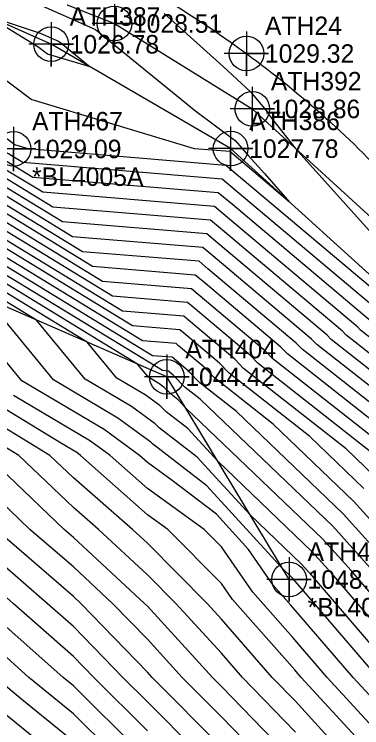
# Model space of a CAD drawing. Extents: x 1213164 to 1213550, y 766120 to 766870.
# Drawn here: x 1213252 to 1213299, y 766303.2 to 766399.6 of the extents above; entities that cross this region are included whole.
import ezdxf

# ---------------------------------------------------------------- set-up
doc = ezdxf.new("R2010")
doc.units = 0
for name, color, linetype in [('Default', 7, 'Continuous'), ('Exist DTM Breakline', 7, 'Continuous'), ('Exist DTM Breakline Cogo Comment', 7, 'Continuous'), ('Exist DTM Breakline Cogo Elevation', 7, 'Continuous'), ('Exist DTM Breakline Cogo Number', 7, 'Continuous'), ('Exist DTM Breakline Cogo Point CELL', 7, 'Continuous'), ('Exist DTM QL2 LIDAR Elevation Point', 7, 'Continuous'), ('Exist DTM Regular Point Cogo Elevation', 7, 'Continuous'), ('Exist DTM Regular Point Cogo Number', 7, 'Continuous'), ('Exist Roads EOP', 7, 'Continuous'), ('Exist Roads EOP Cogo Point CELL', 7, 'Continuous')]:
    doc.layers.add(name, color=color, linetype=linetype)

msp = doc.modelspace()

# ---------------------------------------------------------------- linework, layer by layer
at = {"layer": 'Default'}
for points in [[(1213302.597, 766358.408), (1213282.153, 766375.636), (1213280.103, 766377.363), (1213253.141, 766379.599), (1213251.598, 766380.538), (1213251.233, 766380.76), (1213231.678, 766390.516), (1213231.474, 766390.617), (1213230.808, 766390.964), (1213207.579, 766408.748)], [(1213252.099, 766381.968), (1213238.569, 766392.051), (1213230.917, 766396.699), (1213230.271, 766397.092), (1213210.05, 766409.212)], [(1213300.518, 766357.868), (1213281.492, 766373.902), (1213279.584, 766375.509), (1213254.492, 766377.59), (1213251.259, 766379.558), (1213250.495, 766380.022), (1213231.934, 766389.283), (1213230.499, 766389.988), (1213225.821, 766392.426), (1213206.352, 766407.332)], [(1213304.578, 766352.413), (1213298.807, 766356.947), (1213298.439, 766357.329), (1213280.831, 766372.168), (1213279.065, 766373.656), (1213255.843, 766375.581), (1213250.92, 766378.578), (1213249.758, 766379.285), (1213232.19, 766388.05), (1213229.523, 766389.36), (1213220.835, 766393.889), (1213205.126, 766405.916)], [(1213304.23, 766350.488), (1213296.832, 766356.3), (1213296.361, 766356.79), (1213280.17, 766370.434), (1213278.547, 766371.802), (1213257.194, 766373.572), (1213250.581, 766377.597), (1213249.02, 766378.548), (1213232.445, 766386.817), (1213228.548, 766388.731), (1213215.848, 766395.352), (1213203.899, 766404.5)], [(1213248.618, 766403.962), (1213263.002, 766397.56), (1213276.559, 766386.527), (1213281.848, 766382.566), (1213283.669, 766380.515), (1213285.825, 766378.11), (1213289.231, 766374.252), (1213283.474, 766379.104), (1213281.14, 766381.071), (1213276.351, 766381.468), (1213254.307, 766388.113), (1213246.883, 766393.646), (1213230.055, 766403.868)], [(1213303.882, 766348.563), (1213294.857, 766355.653), (1213294.282, 766356.251), (1213279.509, 766368.7), (1213278.028, 766369.948), (1213258.545, 766371.563), (1213250.242, 766376.617), (1213248.282, 766377.811), (1213232.701, 766385.584), (1213227.572, 766388.103), (1213210.861, 766396.814), (1213202.672, 766403.084)], [(1213303.534, 766346.638), (1213292.883, 766355.006), (1213292.204, 766355.711), (1213278.849, 766366.966), (1213277.51, 766368.094), (1213259.896, 766369.555), (1213249.903, 766375.637), (1213247.544, 766377.073), (1213232.957, 766384.351), (1213226.597, 766387.474), (1213205.874, 766398.277), (1213201.445, 766401.668)], [(1213305.353, 766325.548), (1213297.859, 766333.832), (1213287.001, 766344.237), (1213279.059, 766350.477), (1213277.654, 766351.936), (1213274.223, 766354.827), (1213273.879, 766355.117), (1213269.354, 766355.492), (1213247.531, 766368.776), (1213242.379, 766371.912), (1213234.746, 766375.72), (1213219.769, 766383.075), (1213206.226, 766390.135), (1213197.148, 766393.231), (1213195.169, 766395.169), (1213190, 766397.563), (1213181.204, 766400)], [(1213299.261, 766335.539), (1213291.938, 766342.557), (1213281.033, 766351.124), (1213279.733, 766352.475), (1213274.884, 766356.561), (1213274.398, 766356.971), (1213268.003, 766357.501), (1213247.87, 766369.756), (1213243.117, 766372.649), (1213234.49, 766376.953), (1213220.745, 766383.704), (1213205.157, 766391.829), (1213197.638, 766394.394), (1213195.999, 766395.999), (1213190, 766398.778), (1213185.588, 766400)], [(1213300.664, 766337.246), (1213296.875, 766340.877), (1213283.008, 766351.771), (1213281.811, 766353.015), (1213275.545, 766358.295), (1213274.916, 766358.825), (1213266.652, 766359.51), (1213248.209, 766370.736), (1213243.855, 766373.387), (1213234.235, 766378.186), (1213221.72, 766384.332), (1213204.087, 766393.524), (1213198.128, 766395.556), (1213196.828, 766396.828), (1213190, 766399.992)], [(1213301.812, 766339.197), (1213284.983, 766352.418), (1213283.89, 766353.554), (1213276.205, 766360.029), (1213275.435, 766360.679), (1213265.301, 766361.519), (1213248.548, 766371.716), (1213244.593, 766374.124), (1213233.979, 766379.419), (1213222.695, 766384.961), (1213203.018, 766395.218), (1213198.618, 766396.719), (1213197.658, 766397.658), (1213192.603, 766400)], [(1213302.49, 766340.863), (1213286.958, 766353.065), (1213285.968, 766354.093), (1213276.866, 766361.763), (1213275.954, 766362.533), (1213263.95, 766363.528), (1213248.887, 766372.697), (1213245.33, 766374.861), (1213233.723, 766380.652), (1213223.671, 766385.589), (1213201.949, 766396.913), (1213199.107, 766397.882), (1213198.488, 766398.488), (1213195.224, 766400)], [(1213302.838, 766342.788), (1213288.933, 766353.712), (1213288.047, 766354.633), (1213277.527, 766363.498), (1213276.472, 766364.386), (1213262.599, 766365.537), (1213249.226, 766373.677), (1213246.068, 766375.599), (1213233.468, 766381.885), (1213224.646, 766386.218), (1213200.879, 766398.607), (1213199.597, 766399.044), (1213199.318, 766399.318), (1213197.845, 766400)], [(1213303.186, 766344.713), (1213290.908, 766354.359), (1213290.125, 766355.172), (1213278.188, 766365.232), (1213276.991, 766366.24), (1213261.247, 766367.546), (1213249.565, 766374.657), (1213246.806, 766376.336), (1213233.212, 766383.118), (1213225.622, 766386.846), (1213200.887, 766399.74)], [(1213272.272, 766399.731), (1213280.232, 766392.588), (1213283.937, 766389.169), (1213286.04, 766386.643), (1213286.445, 766385.984), (1213289.983, 766381.545), (1213300.378, 766369.945), (1213306.105, 766363.459), (1213307.084, 766362.361), (1213307.878, 766360.911), (1213311.788, 766354.346), (1213317.801, 766342.795), (1213307.366, 766355.984), (1213305.622, 766358.189), (1213304.732, 766358.888), (1213304.675, 766358.947), (1213282.813, 766377.37), (1213280.621, 766379.217), (1213253.863, 766381.436), (1213252.099, 766381.968)], [(1213302.744, 766325.175), (1213296.457, 766332.125), (1213282.064, 766345.917), (1213277.084, 766349.83), (1213275.576, 766351.397), (1213273.562, 766353.093), (1213273.36, 766353.263), (1213270.705, 766353.484), (1213247.193, 766367.796), (1213241.641, 766371.175), (1213235.002, 766374.487), (1213218.794, 766382.447), (1213207.296, 766388.441), (1213196.658, 766392.069), (1213194.339, 766394.339), (1213190, 766396.349), (1213181.218, 766398.782), (1213180, 766398.685), (1213170.991, 766399.009), (1213170, 766398.972)], [(1213248.178, 766399.505), (1213255.505, 766397.074), (1213258.06, 766395.937), (1213262.243, 766392.532), (1213256.515, 766394.259), (1213255.196, 766395.241), (1213248.178, 766399.505)], [(1213300.135, 766324.802), (1213295.055, 766330.418), (1213277.127, 766347.598), (1213275.109, 766349.183), (1213273.497, 766350.858), (1213272.902, 766351.359), (1213272.842, 766351.41), (1213272.057, 766351.475), (1213246.854, 766366.815), (1213240.903, 766370.437), (1213235.257, 766373.254), (1213217.818, 766381.818), (1213208.365, 766386.746), (1213196.168, 766390.906), (1213193.509, 766393.509), (1213190, 766395.135), (1213182.897, 766397.103), (1213180, 766396.872), (1213172.872, 766397.128), (1213170, 766397.021)], [(1213303.716, 766317.22), (1213297.526, 766324.429), (1213293.652, 766328.711), (1213275.153, 766346.438), (1213274.173, 766347.51), (1213273.467, 766348.054), (1213272.271, 766349.201), (1213271.551, 766349.728), (1213270.143, 766350.562), (1213268.666, 766352.352), (1213246.515, 766365.835), (1213240.165, 766369.7), (1213235.513, 766372.021), (1213216.843, 766381.19), (1213209.435, 766385.052), (1213195.678, 766389.743), (1213192.68, 766392.68), (1213190, 766393.921), (1213184.577, 766395.423), (1213180, 766395.058), (1213174.753, 766395.247), (1213170, 766395.07)], [(1213302.619, 766315.088), (1213294.917, 766324.056), (1213292.25, 766327.004), (1213279.514, 766339.209), (1213275.46, 766343.643), (1213272.538, 766345.896), (1213271.662, 766346.735), (1213269.701, 766348.17), (1213265.866, 766350.443), (1213261.842, 766355.319), (1213246.176, 766364.855), (1213239.428, 766368.963), (1213235.769, 766370.788), (1213215.868, 766380.561), (1213210.504, 766383.357), (1213195.188, 766388.581), (1213191.85, 766391.85), (1213190, 766392.707), (1213186.256, 766393.744), (1213180, 766393.245), (1213176.634, 766393.366), (1213170, 766393.119)], [(1213301.521, 766312.955), (1213292.308, 766323.683), (1213290.848, 766325.297), (1213283.875, 766331.98), (1213276.747, 766339.777), (1213271.609, 766343.737), (1213271.054, 766344.269), (1213267.852, 766346.612), (1213261.588, 766350.323), (1213255.019, 766358.286), (1213245.837, 766363.875), (1213238.69, 766368.225), (1213236.024, 766369.555), (1213214.892, 766379.933), (1213211.573, 766381.663), (1213194.698, 766387.418), (1213191.02, 766391.02), (1213190, 766391.492), (1213187.936, 766392.064), (1213180, 766391.432), (1213178.515, 766391.485), (1213170, 766391.167)], [(1213288.488, 766300), (1213280, 766308.773), (1213278.784, 766310), (1213270, 766319.601), (1213269.614, 766320), (1213260, 766328.926), (1213258.753, 766330), (1213250, 766338.319), (1213247.903, 766340), (1213240, 766345.208), (1213232.477, 766350), (1213230, 766351.086), (1213226.405, 766353.595), (1213220, 766357.02), (1213214.108, 766360), (1213210, 766361.775), (1213206.237, 766363.763), (1213200, 766366.795), (1213193.559, 766370), (1213190, 766371.524), (1213188.255, 766371.745), (1213180, 766373.266), (1213176.341, 766373.659), (1213170, 766374.624)], [(1213280, 766300.545), (1213270.63, 766310), (1213270, 766310.688), (1213260.995, 766320), (1213260, 766320.923), (1213253.326, 766326.674), (1213250, 766329.544), (1213249.402, 766330), (1213240, 766337.619), (1213236.293, 766340), (1213230, 766343.799), (1213221.541, 766348.459), (1213220, 766349.323), (1213218.726, 766350), (1213210, 766354.505), (1213206.367, 766356.367), (1213200, 766359.619), (1213199.265, 766360), (1213190, 766364.587), (1213184.041, 766365.959), (1213180, 766367.027), (1213171.308, 766368.692), (1213170, 766368.959)], [(1213276.631, 766300), (1213270, 766306.688), (1213266.673, 766310), (1213260, 766316.88), (1213256.467, 766320), (1213250, 766325.581), (1213244.199, 766330), (1213240, 766333.403), (1213230.486, 766339.514), (1213230, 766339.835), (1213229.895, 766339.895), (1213229.716, 766340), (1213220, 766345.451), (1213211.434, 766350), (1213210, 766350.74), (1213203.878, 766353.878), (1213200, 766355.859), (1213191.999, 766360), (1213190, 766360.99), (1213188.714, 766361.286), (1213180, 766363.589), (1213175.561, 766364.439), (1213170, 766365.577)], [(1213270, 766302.77), (1213262.739, 766310), (1213260, 766312.824), (1213251.874, 766320), (1213250, 766321.617), (1213243.209, 766326.791), (1213240, 766329.186), (1213238.829, 766330), (1213230, 766335.826), (1213227.335, 766337.335), (1213222.813, 766340), (1213220, 766341.578), (1213216.634, 766343.366), (1213210, 766346.896), (1213204.099, 766350), (1213201.389, 766351.389), (1213200, 766352.098), (1213195.651, 766354.349), (1213190, 766356.816), (1213180.571, 766360), (1213180, 766360.151), (1213179.813, 766360.187), (1213170, 766362.194)], [(1213300.423, 766310.822), (1213289.699, 766323.31), (1213289.445, 766323.59), (1213288.235, 766324.75), (1213278.033, 766335.91), (1213270.68, 766341.579), (1213270.445, 766341.803), (1213266.002, 766345.054), (1213257.311, 766350.204), (1213248.195, 766361.253)], [(1213268.891, 766300), (1213260, 766308.854), (1213258.598, 766310), (1213250, 766317.59), (1213246.649, 766320), (1213240, 766324.962), (1213232.752, 766330), (1213230, 766331.816), (1213224.775, 766334.775), (1213220, 766337.59), (1213215.698, 766340), (1213210, 766343.032), (1213203.604, 766346.396), (1213200, 766348.087), (1213195.55, 766350), (1213190, 766352.422), (1213186.342, 766353.658), (1213180, 766356.001), (1213171.968, 766358.032), (1213170, 766358.69)], [(1213300, 766307.643), (1213297.837, 766310), (1213289.373, 766319.768), (1213286.982, 766322.466), (1213283.668, 766327.287), (1213279.32, 766332.043), (1213273.37, 766336.63), (1213270, 766339.051), (1213268.931, 766340), (1213264.152, 766343.497), (1213253.033, 766350.085), (1213247.455, 766356.846)], [(1213265.104, 766300), (1213260, 766305.082), (1213253.986, 766310), (1213250, 766313.518), (1213240.988, 766320), (1213240, 766320.738), (1213237.58, 766322.42), (1213230, 766327.738), (1213226.127, 766330), (1213222.215, 766332.215), (1213220, 766333.521), (1213211.993, 766338.007), (1213210, 766339.037), (1213209.334, 766339.334), (1213208.013, 766340), (1213200, 766343.759), (1213193.406, 766346.594), (1213190, 766347.998), (1213184.923, 766350), (1213180, 766351.819), (1213177.565, 766352.435), (1213170, 766354.961)], [(1213260, 766301.311), (1213252.811, 766307.189), (1213250, 766309.475), (1213249.199, 766310), (1213240, 766316.542), (1213235.135, 766320), (1213230, 766323.602), (1213221.338, 766328.662), (1213220, 766329.432), (1213218.836, 766330), (1213210, 766334.564), (1213206.242, 766336.242), (1213200, 766339.388), (1213198.575, 766340), (1213190, 766343.534), (1213184.165, 766345.835), (1213180, 766347.509), (1213173.693, 766350), (1213170, 766351.233)], [(1213300, 766303.809), (1213294.32, 766310), (1213289.655, 766315.384), (1213284.236, 766321.496), (1213280, 766327.658), (1213277.68, 766330), (1213270, 766335.517), (1213264.953, 766340), (1213262.303, 766341.939), (1213251.894, 766348.106)], [(1213256.902, 766300), (1213250, 766305.613), (1213243.308, 766310), (1213240, 766312.352), (1213231.867, 766318.133), (1213230, 766319.462), (1213229.055, 766320), (1213220, 766325.211), (1213210.178, 766330), (1213210, 766330.092), (1213203.15, 766333.15), (1213200, 766334.738), (1213191.698, 766338.302), (1213190, 766339.065), (1213187.713, 766340), (1213180, 766343.099), (1213174.877, 766345.123), (1213170, 766347.129)], [(1213299.715, 766300.285), (1213290.802, 766310), (1213289.936, 766311), (1213281.489, 766320.526), (1213280, 766322.693), (1213272.76, 766330), (1213270, 766331.982), (1213260.974, 766340), (1213260.453, 766340.381), (1213258.406, 766341.594), (1213250, 766346.698)], [(1213296.168, 766300), (1213290, 766306.773), (1213286.88, 766310), (1213280, 766317.881), (1213278.068, 766320), (1213270, 766328.131), (1213267.977, 766330), (1213260, 766336.963), (1213256.819, 766340), (1213250, 766344.141)], [(1213290, 766302.592), (1213282.837, 766310), (1213280, 766313.25), (1213273.845, 766320), (1213270, 766323.875), (1213263.37, 766330), (1213260, 766332.942), (1213252.608, 766340), (1213250, 766341.583)], [(1213284.508, 766300), (1213280, 766304.659), (1213274.707, 766310), (1213270, 766315.144), (1213265.304, 766320), (1213260, 766324.925), (1213254.11, 766330), (1213250, 766333.906)]]:
    msp.add_lwpolyline(points, dxfattribs=at)
at = {"layer": 'Exist DTM Breakline'}
for points in [[(1213422.776, 766171.254), (1213409.831, 766196.926), (1213386.657, 766233.346), (1213364.326, 766270.025), (1213348.91, 766295.975), (1213348.91, 766295.975), (1213325.275, 766332.542), (1213305.812, 766359.242), (1213281.253, 766381.475), (1213256.992, 766395.586), (1213227.813, 766408.558), (1213197.433, 766416.071)], [(1213246.745, 766405.836), (1213265.533, 766398.391), (1213284.184, 766386.845), (1213308.14, 766364.949), (1213319.74, 766349.721)], [(1213289.151, 766323.232), (1213272.624, 766350.631), (1213236.71, 766366.247), (1213213.309, 766378.913), (1213194.382, 766386.667)]]:
    msp.add_lwpolyline(points, dxfattribs=at)
at = {"layer": 'Exist DTM Breakline Cogo Point CELL'}
for points in [[(1213265.533, 766401.391), (1213265.533, 766395.391), (1213265.533, 766398.391), (1213268.533, 766398.391), (1213262.533, 766398.391)], [(1213256.992, 766398.586), (1213256.992, 766392.586), (1213256.992, 766395.586), (1213259.992, 766395.586), (1213253.992, 766395.586)], [(1213284.184, 766389.845), (1213284.184, 766383.845), (1213284.184, 766386.845), (1213287.184, 766386.845), (1213281.184, 766386.845)], [(1213251.907, 766384.433), (1213251.907, 766378.433), (1213251.907, 766381.433), (1213254.907, 766381.433), (1213248.907, 766381.433)], [(1213281.253, 766384.475), (1213281.253, 766378.475), (1213281.253, 766381.475), (1213284.253, 766381.475), (1213278.253, 766381.475)], [(1213272.624, 766353.631), (1213272.624, 766347.631), (1213272.624, 766350.631), (1213275.624, 766350.631), (1213269.624, 766350.631)], [(1213289.151, 766326.232), (1213289.151, 766320.232), (1213289.151, 766323.232), (1213292.151, 766323.232), (1213286.151, 766323.232)]]:
    msp.add_lwpolyline(points, dxfattribs=at)
for centre in [(1213265.533, 766398.391), (1213256.992, 766395.586), (1213284.184, 766386.845), (1213251.907, 766381.433), (1213281.253, 766381.475), (1213272.624, 766350.631), (1213289.151, 766323.232)]:
    msp.add_circle(centre, 2.344, dxfattribs=at)
at = {"layer": 'Exist DTM QL2 LIDAR Elevation Point'}
for p, q in [((1213260, 766340), (1213260, 766340)), ((1213270, 766340), (1213270, 766340)), ((1213260, 766330), (1213260, 766330)), ((1213270, 766330), (1213270, 766330)), ((1213280, 766330), (1213280, 766330)), ((1213260, 766320), (1213260, 766320)), ((1213270, 766320), (1213270, 766320)), ((1213280, 766320), (1213280, 766320)), ((1213260, 766310), (1213260, 766310)), ((1213270, 766310), (1213270, 766310)), ((1213280, 766310), (1213280, 766310)), ((1213290, 766310), (1213290, 766310))]:
    msp.add_line(p, q, dxfattribs=at)
at = {"layer": 'Exist Roads EOP'}
msp.add_spline([(1213169.012, 766424.202), (1213197.361, 766422.679), (1213222.732, 766418.674), (1213259.828, 766408.159), (1213283.389, 766394.331), (1213303.908, 766375.84), (1213322.371, 766351.308)], degree=3, dxfattribs=at)
at = {"layer": 'Exist Roads EOP Cogo Point CELL'}
msp.add_lwpolyline([(1213283.389, 766397.331), (1213283.389, 766391.331), (1213283.389, 766394.331), (1213286.389, 766394.331), (1213280.389, 766394.331)], dxfattribs=at)
msp.add_circle((1213283.389, 766394.331), 2.344, dxfattribs=at)

# ---------------------------------------------------------------- texts
at = {"layer": 'Exist DTM Breakline Cogo Comment'}
for s, p in [('*BL4005A', (1213254.407, 766376.433)), ('*BL4005', (1213291.651, 766318.232))]:
    msp.add_text(s, height=2.5, dxfattribs=at).set_placement(p)
at = {"layer": 'Exist DTM Breakline Cogo Elevation'}
for s, p in [('1028.51', (1213268.033, 766397.141)), ('1026.78', (1213259.492, 766394.336)), ('1028.86', (1213286.684, 766385.595)), ('1029.09', (1213254.407, 766380.183)), ('1027.78', (1213283.753, 766380.225)), ('1044.42', (1213275.124, 766349.381)), ('1048.21', (1213291.651, 766321.982))]:
    msp.add_text(s, height=2.5, dxfattribs=at).set_placement(p)
at = {"layer": 'Exist DTM Breakline Cogo Number'}
for s, p in [('ATH387', (1213259.492, 766398.086)), ('ATH392', (1213286.684, 766389.345)), ('ATH467', (1213254.407, 766383.933)), ('ATH386', (1213283.753, 766383.975)), ('ATH404', (1213275.124, 766353.131)), ('ATH403', (1213291.651, 766325.732))]:
    msp.add_text(s, height=2.5, dxfattribs=at).set_placement(p)
at = {"layer": 'Exist DTM Regular Point Cogo Elevation'}
msp.add_text('1029.32', height=2.5, dxfattribs=at).set_placement((1213285.889, 766393.081))
at = {"layer": 'Exist DTM Regular Point Cogo Number'}
msp.add_text('ATH24', height=2.5, dxfattribs=at).set_placement((1213285.889, 766396.831))

doc.saveas('drawing.dxf')
